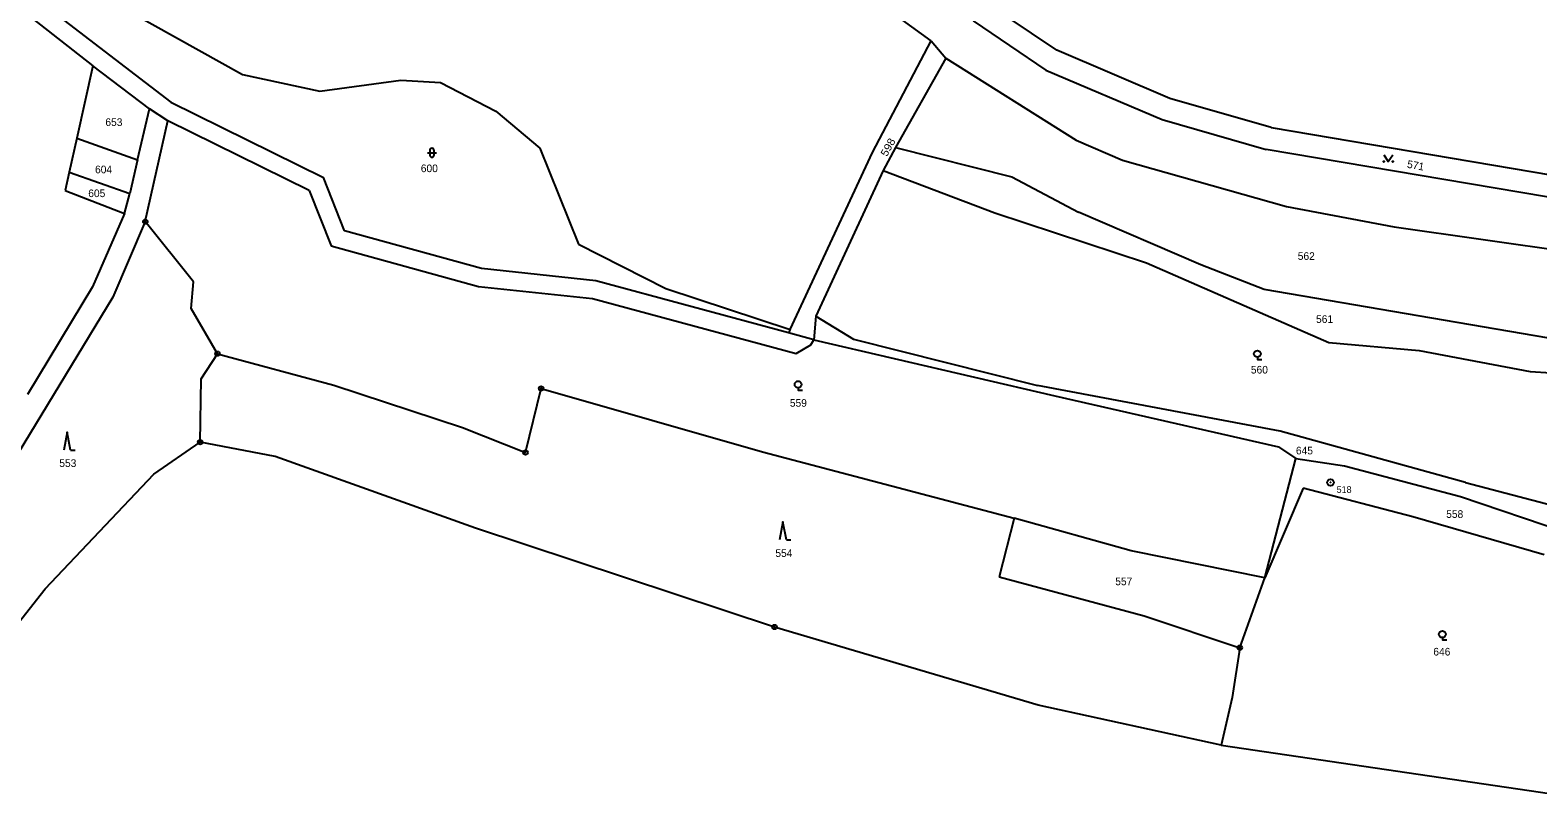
# Model space of a CAD drawing. Extents: x -759947 to -757003, y -1019641 to -1017100.
# Drawn here: x -758601.9 to -758266.2, y -1019125.7 to -1018953.1 of the extents above; entities that cross this region are included whole.
import ezdxf

# ---------------------------------------------------------------- set-up
doc = ezdxf.new("R2010")
doc.units = 0
doc.header["$LTSCALE"] = 0.68
for name, color, linetype, lineweight in [('1', 7, 'Continuous', 25), ('3', 7, 'Continuous', 25), ('8', 7, 'Continuous', 25)]:
    doc.layers.add(name, color=color, linetype=linetype, lineweight=lineweight)
doc.layers.add('2', color=7, linetype='Continuous')

msp = doc.modelspace()

# ---------------------------------------------------------------- linework, layer by layer
at = {"layer": '1'}
for p, q in [((-758401.22, -1018955.48), (-758454.02, -1018917.2)), ((-758373.27, -1018957.61), (-758390.19, -1018946.19)), ((-758598.79, -1018947.47), (-758570.55, -1018969.19)), ((-758579.2, -1018949.27), (-758554.61, -1018963.04)), ((-758601.27, -1018950.61), (-758587.92, -1018961.07)), ((-758391.9, -1018951.06), (-758375.67, -1018962.02)), ((-758414.32, -1018980.37), (-758401.22, -1018955.48)), ((-758401.22, -1018955.48), (-758397.96, -1018959.4)), ((-758397.96, -1018959.4), (-758409.19, -1018979.26)), ((-758397.96, -1018959.4), (-758368.92, -1018977.62)), ((-758348.13, -1018968.33), (-758373.27, -1018957.61)), ((-758587.92, -1018961.07), (-758591.48, -1018977.15)), ((-758575.28, -1018970.63), (-758587.92, -1018961.07)), ((-758554.61, -1018963.04), (-758537.34, -1018966.71)), ((-758375.67, -1018962.02), (-758349.81, -1018973.05)), ((-758537.34, -1018966.71), (-758519.29, -1018964.25)), ((-758519.29, -1018964.25), (-758510.5, -1018964.76)), ((-758510.5, -1018964.76), (-758498.19, -1018971.14)), ((-758570.55, -1018969.19), (-758536.57, -1018985.9)), ((-758325.52, -1018974.81), (-758348.13, -1018968.33)), ((-758577.93, -1018981.98), (-758575.28, -1018970.63)), ((-758576.22, -1018995.75), (-758571.22, -1018973.32)), ((-758571.22, -1018973.32), (-758575.28, -1018970.63)), ((-758539.72, -1018988.81), (-758571.22, -1018973.32)), ((-758498.19, -1018971.14), (-758488.34, -1018979.38)), ((-758349.81, -1018973.05), (-758326.63, -1018979.69)), ((-758591.48, -1018977.15), (-758593.17, -1018984.76)), ((-758591.48, -1018977.15), (-758577.93, -1018981.98)), ((-758325.52, -1018974.81), (-758253.97, -1018986.89)), ((-758488.34, -1018979.38), (-758479.79, -1019000.78)), ((-758432.65, -1019019.73), (-758414.32, -1018980.37)), ((-758409.19, -1018979.26), (-758411.91, -1018984.33)), ((-758409.19, -1018979.26), (-758383.31, -1018985.78)), ((-758368.92, -1018977.62), (-758358.61, -1018982.08)), ((-758254.89, -1018991.81), (-758326.63, -1018979.69)), ((-758577.93, -1018981.98), (-758579.67, -1018989.46)), ((-758358.61, -1018982.08), (-758322.09, -1018992.4)), ((-758593.17, -1018984.76), (-758594.07, -1018988.81)), ((-758593.17, -1018984.76), (-758579.67, -1018989.46)), ((-758531.86, -1018997.82), (-758536.57, -1018985.9)), ((-758411.91, -1018984.33), (-758426.92, -1019016.75)), ((-758411.91, -1018984.33), (-758387.04, -1018993.78)), ((-758383.31, -1018985.78), (-758368.47, -1018993.61)), ((-758594.07, -1018988.81), (-758580.87, -1018993.92)), ((-758580.87, -1018993.92), (-758579.67, -1018989.46)), ((-758539.72, -1018988.81), (-758534.86, -1019001.11)), ((-758580.87, -1018993.92), (-758587.95, -1019010.27)), ((-758387.04, -1018993.78), (-758353.31, -1019004.9)), ((-758341.19, -1019005.38), (-758368.47, -1018993.61)), ((-758322.09, -1018992.4), (-758298.14, -1018996.9)), ((-758576.22, -1018995.75), (-758583.47, -1019012.53)), ((-758565.47, -1019009.16), (-758576.22, -1018995.75)), ((-758298.14, -1018996.9), (-758245.93, -1019004.36)), ((-758501.35, -1019006.21), (-758531.86, -1018997.82)), ((-758479.79, -1019000.78), (-758460.35, -1019010.59)), ((-758534.86, -1019001.11), (-758502.05, -1019010.16)), ((-758475.89, -1019008.9), (-758501.35, -1019006.21)), ((-758353.31, -1019004.9), (-758312.7, -1019022.63)), ((-758327.08, -1019010.81), (-758341.19, -1019005.38)), ((-758587.95, -1019010.27), (-758602.45, -1019034.21)), ((-758565.98, -1019015.08), (-758565.47, -1019009.16)), ((-758502.05, -1019010.16), (-758476.63, -1019012.85)), ((-758432.99, -1019020.47), (-758475.89, -1019008.9)), ((-758460.35, -1019010.59), (-758432.65, -1019019.73)), ((-758266.77, -1019021.13), (-758327.08, -1019010.81)), ((-758583.47, -1019012.53), (-758608.51, -1019053.87)), ((-758476.63, -1019012.85), (-758431.3, -1019025.07)), ((-758560.14, -1019025.14), (-758565.98, -1019015.08)), ((-758426.92, -1019016.75), (-758427.35, -1019022.01)), ((-758426.92, -1019016.75), (-758418.55, -1019021.92)), ((-758432.65, -1019019.73), (-758432.99, -1019020.47)), ((-758427.35, -1019022.01), (-758432.99, -1019020.47)), ((-758431.3, -1019025.07), (-758428.04, -1019023.19)), ((-758428.04, -1019023.19), (-758427.35, -1019022.01)), ((-758427.35, -1019022.01), (-758373.7, -1019034.54)), ((-758418.55, -1019021.92), (-758377.57, -1019032.23)), ((-758312.7, -1019022.63), (-758292.6, -1019024.41)), ((-758245.79, -1019024.85), (-758266.77, -1019021.13)), ((-758563.76, -1019030.7), (-758560.14, -1019025.14)), ((-758560.14, -1019025.14), (-758534.25, -1019032.13)), ((-758292.6, -1019024.41), (-758267.87, -1019029.06)), ((-758564, -1019044.8), (-758563.76, -1019030.7)), ((-758267.87, -1019029.06), (-758245.75, -1019030.6)), ((-758534.25, -1019032.13), (-758505.58, -1019041.54)), ((-758491.56, -1019047.12), (-758488.09, -1019032.86)), ((-758488.09, -1019032.86), (-758438.8, -1019046.99)), ((-758323.55, -1019042.36), (-758377.57, -1019032.23)), ((-758373.7, -1019034.54), (-758323.9, -1019045.87)), ((-758505.58, -1019041.54), (-758491.56, -1019047.12)), ((-758282.3, -1019053.8), (-758323.55, -1019042.36)), ((-758574.35, -1019051.95), (-758564, -1019044.8)), ((-758547.33, -1019047.98), (-758564, -1019044.8)), ((-758438.8, -1019046.99), (-758382.76, -1019061.74)), ((-758323.9, -1019045.87), (-758320.03, -1019048.46)), ((-758502.69, -1019063.95), (-758547.33, -1019047.98)), ((-758326.92, -1019074.97), (-758320.03, -1019048.46)), ((-758320.03, -1019048.46), (-758309.17, -1019050.12)), ((-758309.17, -1019050.12), (-758283.39, -1019056.93)), ((-758598.52, -1019077.46), (-758574.35, -1019051.95)), ((-758282.3, -1019053.8), (-758245.52, -1019063.39)), ((-758318.39, -1019055.04), (-758326.92, -1019074.97)), ((-758293.97, -1019061.4), (-758318.39, -1019055.04)), ((-758283.39, -1019056.93), (-758260.11, -1019064.79)), ((-758436.14, -1019085.96), (-758502.69, -1019063.95)), ((-758382.76, -1019061.74), (-758386.08, -1019074.76)), ((-758356.68, -1019068.97), (-758382.76, -1019061.74)), ((-758264.75, -1019069.91), (-758293.97, -1019061.4)), ((-758326.92, -1019074.97), (-758356.68, -1019068.97)), ((-758628.12, -1019114.94), (-758598.52, -1019077.46)), ((-758386.08, -1019074.76), (-758353.8, -1019083.44)), ((-758332.52, -1019090.55), (-758326.92, -1019074.97)), ((-758353.8, -1019083.44), (-758332.52, -1019090.55)), ((-758377.41, -1019103.32), (-758436.14, -1019085.96)), ((-758332.52, -1019090.55), (-758334.23, -1019101.66)), ((-758336.68, -1019112.26), (-758377.41, -1019103.32)), ((-758334.23, -1019101.66), (-758336.68, -1019112.26)), ((-758336.68, -1019112.26), (-758245.09, -1019125.74))]:
    msp.add_line(p, q, dxfattribs=at)
at = {"layer": '3'}
for p, q in [((-758513.401, -1018980.431), (-758511.399, -1018980.431)), ((-758512.901, -1018979.931), (-758512.901, -1018980.932)), ((-758511.899, -1018980.932), (-758511.899, -1018979.931)), ((-758592.85, -1019046.57), (-758591.854, -1019046.57)), ((-758433.48, -1019066.54), (-758432.484, -1019066.54))]:
    msp.add_line(p, q, dxfattribs=at)
for points in [[(-758300.45, -1018980.879), (-758299.45, -1018982.38), (-758298.45, -1018980.879)], [(-758328.61, -1019025.922), (-758328.61, -1019026.42), (-758327.609, -1019026.42)], [(-758430.87, -1019032.712), (-758430.87, -1019033.21), (-758429.869, -1019033.21)], [(-758592.85, -1019046.57), (-758593.6, -1019042.57), (-758594.35, -1019046.57)], [(-758433.48, -1019066.54), (-758434.23, -1019062.54), (-758434.98, -1019066.54)], [(-758287.42, -1019088.312), (-758287.42, -1019088.81), (-758286.419, -1019088.81)]]:
    msp.add_lwpolyline(points, dxfattribs=at)
for centre, radius in [((-758300.45, -1018982.3795), 0.1), ((-758298.45, -1018982.3795), 0.1), ((-758328.6093, -1019025.1709), 0.75), ((-758430.8693, -1019031.9609), 0.75), ((-758287.4193, -1019087.5609), 0.75)]:
    msp.add_circle(centre, radius, dxfattribs=at)
for centre, start, end in [((-758512.4, -1018979.9309), 0, 180), ((-758512.4, -1018980.9309), 180, 359.98789)]:
    msp.add_arc(centre, 0.5, start, end, dxfattribs=at)
at = {"layer": '8'}
for centre, radius in [((-758576.22, -1018995.7499), 0.5), ((-758576.22, -1018995.7499), 0.0303), ((-758560.14, -1019025.1399), 0.5), ((-758560.14, -1019025.1399), 0.0303), ((-758488.09, -1019032.8599), 0.5), ((-758488.09, -1019032.8599), 0.0303), ((-758564, -1019044.7999), 0.5), ((-758564, -1019044.7999), 0.0303), ((-758491.56, -1019047.1199), 0.5), ((-758491.56, -1019047.1199), 0.0303), ((-758312.32, -1019053.7798), 0.75), ((-758312.32, -1019053.7798), 0.03), ((-758436.14, -1019085.9599), 0.5), ((-758436.14, -1019085.9599), 0.0303), ((-758332.52, -1019090.5499), 0.5), ((-758332.52, -1019090.5499), 0.0303)]:
    msp.add_circle(centre, radius, dxfattribs=at)

# ---------------------------------------------------------------- texts
at = {"layer": '2'}
for s, p in [('653', (-758585.11, -1018974.455)), ('604', (-758587.41, -1018984.985)), ('600', (-758514.87, -1018984.735)), ('605', (-758588.92, -1018990.285)), ('562', (-758319.61, -1019004.255)), ('561', (-758315.54, -1019018.285)), ('560', (-758330.05, -1019029.545)), ('559', (-758432.7, -1019036.935)), ('645', (-758320.02, -1019047.535)), ('553', (-758595.37, -1019050.335)), ('558', (-758286.56, -1019061.665)), ('554', (-758435.93, -1019070.355)), ('557', (-758360.25, -1019076.655)), ('646', (-758289.43, -1019092.295))]:
    msp.add_text(s, height=1.7, dxfattribs=at).set_placement(p)
at = {"layer": '2', "width": 1.1}
msp.add_text('598', height=1.7, rotation=61, dxfattribs=at).set_placement((-758411.118, -1018981.426))
at = {"layer": '2'}
msp.add_text('571', height=1.7, rotation=350, dxfattribs=at).set_placement((-758295.363, -1018983.738))
at = {"layer": '8'}
msp.add_text('518', height=1.5, dxfattribs=at).set_placement((-758310.97, -1019056.115))

doc.saveas('drawing.dxf')
